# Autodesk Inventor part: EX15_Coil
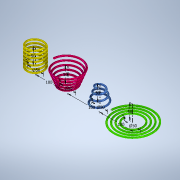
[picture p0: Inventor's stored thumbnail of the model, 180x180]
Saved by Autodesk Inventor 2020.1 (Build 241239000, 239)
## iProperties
Created: 2019-10
Part Number: EX15_Coil
Material: Nickel-Copper Alloy 400
Document SubType Name: Modeling
Designer: Synergysoft Dell02
Density: 8.83 g/cm^3
Appearance: Chrome - Polished
Author: Synergysoft Dell02
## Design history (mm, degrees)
sketch "Sketch1"
  geometry: L1 (0, 0)-(0, 50); L2 (-100, 0)-(-100, 50); L3 (100, 0)-(100, 50); L4 (200, 0)-(200, 50); C1 r 2.5 at (-25, 0); C2 r 2.5 at (-125, 0); C3 r 2.5 at (75, 0); C4 r 2.5 at (175, 0)
  constraints: 8 end point, 7 horizontal alignment, 4 centre point, 4 vertical
  dimensions: "d0" = 5 diameter of C1; "d1" = 50 distance of L1.start L1.end; "d2" = 50 diameter of C1.centre L1; "d11" = 5 diameter of C2; "d12" = 50 distance of L2.start L2.end; "d13" = 50 diameter of C2.centre L2; "d14" = 5 diameter of C3; "d15" = 50 distance of L3.start L3.end; "d16" = 50 diameter of C3.centre L3; "d17" = 5 diameter of C4; "d18" = 50 distance of L4.start L4.end; "d19" = 50 diameter of C4.centre L4; "d20" = 100 distance of L1.start L2.start; "d21" = 100 distance of L3.start L1.start; "d22" = 100 distance of L4.start L3.start
coil "Coil1" pitch "d3" = 10; turns "d5" = 6; dims "d4" = 50, "d6" = 0, angle "d7" = 90 deg, angle "d8" = 90 deg, "d9" = 0, "d10" = 0
coil "Coil2" pitch "d23" = 10; turns "d25" = 5; dims "d24" = 50, "d26" = 20 deg, angle "d27" = 90 deg, angle "d28" = 90 deg, "d29" = 0, "d30" = 0
coil "Coil3" pitch "d31" = 15; turns "d33" = 4; dims "d32" = 50, "d34" = -15 deg, angle "d35" = 90 deg, angle "d36" = 90 deg, "d37" = 0, "d38" = 0
coil "Coil4" pitch "d39" = 10; turns "d41" = 4; dims "d40" = 50, "d42" = 20 deg, angle "d43" = 90 deg, angle "d44" = 90 deg, "d45" = 0, "d46" = 0
body "Solid1"
body "Solid2"
body "Solid3"
body "Solid4"
